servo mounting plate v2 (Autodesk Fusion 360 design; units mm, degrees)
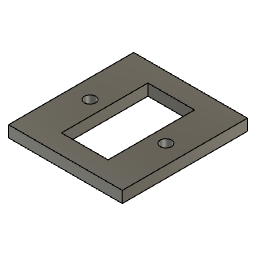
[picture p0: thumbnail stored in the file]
sketch "Sketch1" plane through (0, 0, 0) normal (0, 0, 1) x axis (1, 0, 0)
  line L1 (-15, 16.5) -> (15, 16.5)
  line L2 (-15, -16.5) -> (-15, 16.5)
  line L3 (15, -16.5) -> (-15, -16.5)
  line L4 (15, 16.5) -> (15, -16.5)
  line L5 (-15, -16.5) -> (15, 16.5)
  line L6 (15, -16.5) -> (-15, 16.5)
  point P6 (0, 0)
  point P1 (0, 0)
  point P3 (-15, 16.5)
  point P4 (-15, -16.5)
  point P5 (15, -16.5)
  perpendicular L1 L2
  parallel L1 L3
  parallel L2 L4
  horizontal L1
  coincident L5 P6
  coincident L6 P6
  coincident P1 P6
  dimension "d1" distance P3 P4 = 33
  dimension "d2" distance P4 P5 = 30
extrude "Extrude1" new body sketch "Sketch1" profile of L1 L2 L3 L4 along normal blind 3
sketch "Sketch2" plane through (0, 0, 3) normal (0, 0, 1) x axis (-1, 0, 0)
  line L1 (-15, -16.5) -> (-15, 16.5)
  line L2 (15, -16.5) -> (-15, -16.5)
  line L3 (15, 16.5) -> (15, -16.5)
  line L4 (-15, 16.5) -> (15, 16.5)
  line L5 (6.15, 11.4) -> (-6.15, -11.4)
  line L6 (-6.15, 11.4) -> (6.15, -11.4)
  line L7 (6.15, 11.4) -> (6.15, -11.4)
  line L8 (-6.15, -11.4) -> (-6.15, 11.4)
  line L9 (-6.15, 11.4) -> (6.15, 11.4)
  line L10 (6.15, -11.4) -> (-6.15, -11.4)
  line L11 (-10, 0) -> (0, 0)
  line L12 (0, 11.4) -> (0, 0)
  circle C1 centre (-10, 0) radius 1.5
  circle C2 centre (10, 0) radius 1.5
  point P8 (0, 0)
  point P11 (0, 0)
  point P1 (0, 0)
  point P12 (0, 0)
  point P13 (-10, 0)
  point P14 (-10, 0)
  point P15 (0, 0)
  point P16 (0, 11.4)
  point P6 (-6.15, 11.4)
  point P9 (6.15, 11.4)
  perpendicular L7 L10
  parallel L9 L10
  parallel L7 L8
  horizontal L10
  coincident P8 L5
  coincident P8 L6
  coincident P8 P11
  coincident P1 P8
  coincident P11 P12
  horizontal L11
  coincident P13 P14
  coincident P1 P15
  midpoint L9 P16
  symmetric C1 L12 C2
  dimension "d5" distance L9 L10 = 22.8
  dimension "d6" distance P6 P9 = 12.3
  dimension "d7" distance P12 P13 = 10
  dimension "d8" diameter C1 = 3
extrude "Extrude2" cut sketch "Sketch2" profile of L7 L8 L9 L10 C1 C2 against normal blind 13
